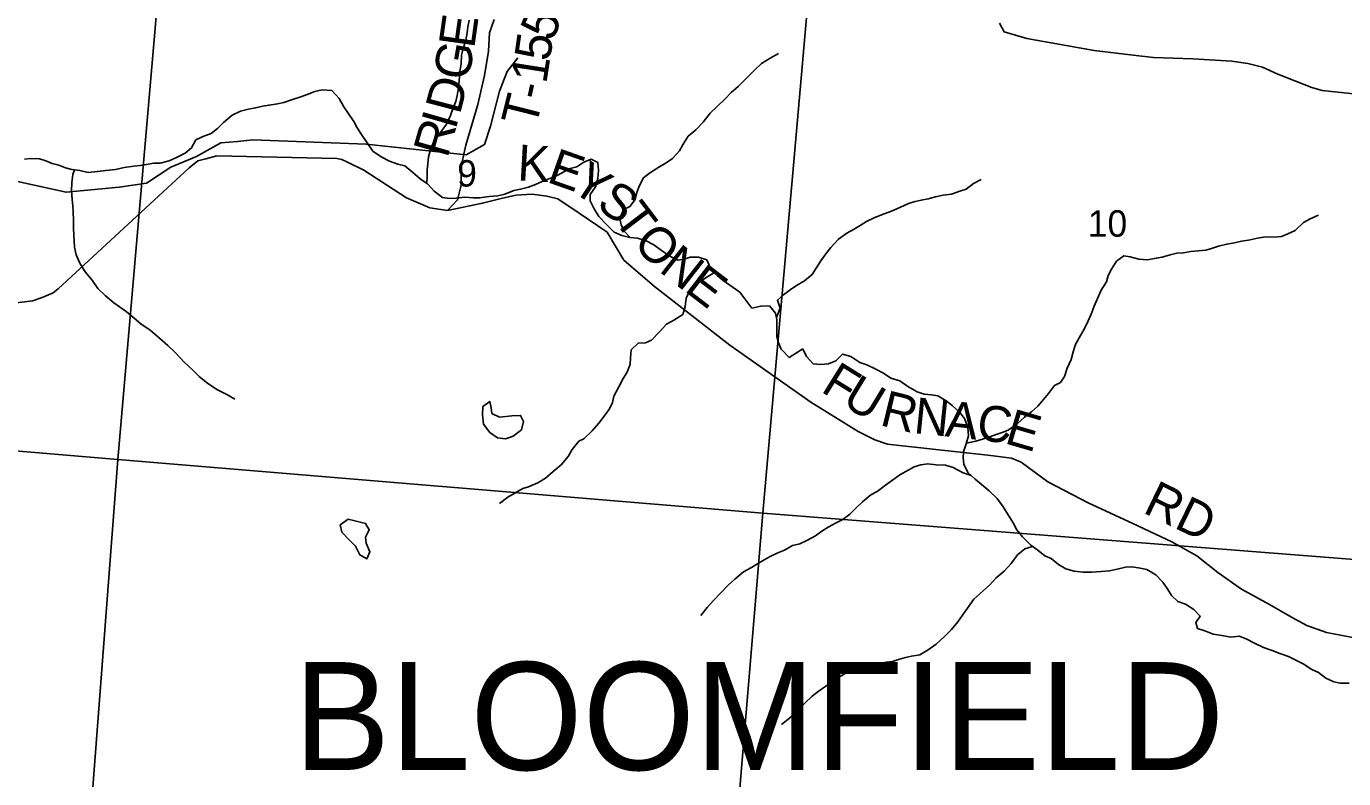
# Model space of a CAD drawing. Extents: x 0 to 42, y 0 to 22.
# Drawn here: x 6.349 to 7.389, y 18.942 to 19.536 of the extents above; entities that cross this region are included whole.
import ezdxf

# ---------------------------------------------------------------- set-up
doc = ezdxf.new("R2010")
doc.units = 0
for name, color, linetype in [('GM_X_County_Road', 7, 'Continuous'), ('GM_X_County_Road_Text', 7, 'Continuous'), ('GM_X_Minor_Lake', 7, 'Continuous'), ('GM_X_Minor_River', 7, 'Continuous'), ('GM_X_Rail_Line', 7, 'Continuous'), ('GM_X_Section', 7, 'Continuous'), ('GM_X_Section_Text', 7, 'Continuous'), ('GM_X_Township_Road', 7, 'Continuous'), ('GM_X_Township_Road_Text', 7, 'Continuous'), ('GM_X_Township_Text', 7, 'Continuous')]:
    doc.layers.add(name, color=color, linetype=linetype)

msp = doc.modelspace()

# ---------------------------------------------------------------- linework, layer by layer
at = {"layer": 'GM_X_County_Road'}
for points in [[(7.1177, 19.5388), (7.1212, 19.532), (7.1391, 19.5267), (7.1924, 19.5172), (7.2231, 19.5135), (7.2391, 19.5118), (7.2702, 19.5107), (7.301, 19.5089), (7.3136, 19.5071), (7.3253, 19.504), (7.3375, 19.4986), (7.3642, 19.488), (7.3723, 19.4858), (7.4098, 19.4816)], [(6.1908, 19.3004), (6.3543, 19.3196), (6.363, 19.3228), (6.3703, 19.3259), (6.3744, 19.329), (6.4778, 19.4246), (6.4845, 19.43), (6.4908, 19.4318), (6.4939, 19.4325), (6.4996, 19.434), (6.5943, 19.432), (6.5983, 19.4311), (6.6029, 19.429), (6.6158, 19.4227), (6.6494, 19.4009), (6.6679, 19.3929), (6.6817, 19.3909), (6.7094, 19.3967), (6.7242, 19.4005), (6.7358, 19.4029), (6.7485, 19.4037), (6.7603, 19.4023), (6.7689, 19.4001), (6.7856, 19.3889), (6.8078, 19.3737), (6.821, 19.3518), (6.8452, 19.3308), (6.9047, 19.2846), (6.9685, 19.2395), (7.0059, 19.2163), (7.0191, 19.2097), (7.0291, 19.2064), (7.0698, 19.202), (7.1083, 19.1976), (7.127, 19.1954), (7.1347, 19.1921), (7.1557, 19.1767), (7.1876, 19.1602), (7.2228, 19.1437), (7.2536, 19.1293), (7.2734, 19.1183), (7.29, 19.1051), (7.3087, 19.0919), (7.3307, 19.0798), (7.3483, 19.0699), (7.3604, 19.0633), (7.3758, 19.0578), (7.4034, 19.0523)]]:
    msp.add_lwpolyline(points, dxfattribs=at)
at = {"layer": 'GM_X_Minor_Lake'}
for points in [[(6.7227, 19.2276), (6.7168, 19.2305), (6.7161, 19.2352), (6.7152, 19.24), (6.7097, 19.2362), (6.7095, 19.2296), (6.7102, 19.2222), (6.7151, 19.2157), (6.7213, 19.2113), (6.7276, 19.2106), (6.7314, 19.212)], [(6.7314, 19.212), (6.7336, 19.2128), (6.7401, 19.2177), (6.7418, 19.2242), (6.7395, 19.2291), (6.7325, 19.2287), (6.7227, 19.2276)], [(6.6032, 19.1473), (6.597, 19.1427), (6.5983, 19.1369), (6.6039, 19.131), (6.609, 19.1258), (6.6124, 19.119), (6.6181, 19.1159), (6.6197, 19.1195)], [(6.6197, 19.1195), (6.6205, 19.1214), (6.6175, 19.1283), (6.617, 19.133), (6.62, 19.1387), (6.617, 19.1438), (6.6032, 19.1473)]]:
    msp.add_lwpolyline(points, dxfattribs=at)
at = {"layer": 'GM_X_Minor_River'}
for points in [[(6.6651, 19.4125), (6.6656, 19.4163), (6.6658, 19.4229), (6.6662, 19.4277), (6.6668, 19.4334), (6.6686, 19.4398), (6.6714, 19.4466), (6.6767, 19.4534), (6.6809, 19.4591), (6.684, 19.4659), (6.6861, 19.472), (6.6882, 19.4769), (6.6893, 19.4818), (6.6905, 19.4875), (6.6909, 19.4932), (6.6915, 19.5004), (6.6924, 19.5069), (6.6928, 19.5135), (6.694, 19.5188), (6.6961, 19.5254), (6.6973, 19.5311), (6.6978, 19.5359), (6.6988, 19.5413)], [(6.826, 19.3697), (6.821, 19.3749), (6.8188, 19.3796), (6.8177, 19.3847), (6.8207, 19.3917), (6.8258, 19.394), (6.83, 19.3997), (6.8312, 19.405), (6.8333, 19.4106), (6.8365, 19.4167), (6.8413, 19.4203), (6.8485, 19.425), (6.8545, 19.4286), (6.8593, 19.432), (6.8648, 19.438), (6.8678, 19.4433), (6.8718, 19.4496), (6.8779, 19.4545), (6.8836, 19.4607), (6.8891, 19.4677), (6.8948, 19.4732), (6.9007, 19.4787), (6.9056, 19.484), (6.9113, 19.4889), (6.9242, 19.5017), (6.9297, 19.5069), (6.9364, 19.5112), (6.9432, 19.5148)], [(6.7893, 19.429), (6.7839, 19.4254), (6.7786, 19.4241), (6.7735, 19.4214), (6.7682, 19.4186), (6.7618, 19.416), (6.7565, 19.4137), (6.7513, 19.4115), (6.7458, 19.4094), (6.7394, 19.4077), (6.7341, 19.4066), (6.7271, 19.4038), (6.7214, 19.4025), (6.7146, 19.4019), (6.7072, 19.4008), (6.7021, 19.401), (6.6955, 19.4014), (6.6885, 19.4007), (6.6836, 19.4005), (6.6779, 19.4011), (6.6711, 19.4061), (6.666, 19.412), (6.6601, 19.4158), (6.6541, 19.4213), (6.6481, 19.4262), (6.6426, 19.4276), (6.636, 19.4299), (6.6294, 19.4333), (6.6228, 19.4377), (6.6184, 19.4443), (6.6139, 19.4508), (6.6105, 19.4563), (6.6079, 19.4613), (6.6034, 19.4677), (6.5998, 19.4729), (6.5962, 19.4793), (6.5904, 19.4856), (6.5828, 19.4862), (6.5769, 19.4849), (6.5709, 19.4826), (6.5659, 19.4807), (6.5586, 19.4783), (6.5525, 19.4762), (6.5474, 19.4751), (6.5408, 19.4742), (6.5358, 19.4733), (6.53, 19.4721), (6.5247, 19.471), (6.5182, 19.4693), (6.5116, 19.4663), (6.5049, 19.4603), (6.5, 19.4556), (6.4951, 19.4516), (6.4892, 19.4495), (6.4831, 19.4467), (6.4795, 19.4403), (6.4746, 19.4361), (6.4678, 19.4327), (6.4619, 19.4301), (6.4549, 19.4284), (6.4496, 19.4282), (6.4441, 19.4273), (6.439, 19.4264), (6.434, 19.426), (6.4265, 19.4249), (6.4197, 19.4234), (6.4119, 19.4225), (6.4053, 19.4216), (6.3981, 19.421), (6.3915, 19.4224), (6.3852, 19.4233), (6.3801, 19.4247), (6.3748, 19.4268), (6.3695, 19.4281), (6.3646, 19.43), (6.3595, 19.4318), (6.3527, 19.432), (6.3478, 19.4314)], [(7.0259, 19.2624), (7.0194, 19.266), (7.0128, 19.2691), (7.0074, 19.271), (7.0002, 19.2756), (6.9936, 19.2775), (6.9884, 19.2722), (6.9826, 19.2698), (6.9763, 19.2694), (6.9706, 19.2698), (6.9653, 19.2755), (6.9623, 19.2816), (6.9572, 19.2785), (6.9515, 19.2748), (6.9451, 19.2814), (6.9432, 19.2864), (6.9419, 19.2913), (6.9418, 19.2985), (6.9418, 19.3049), (6.9408, 19.3099), (6.9359, 19.3156), (6.9291, 19.3154), (6.9221, 19.3137), (6.9172, 19.3202), (6.9125, 19.3263), (6.9074, 19.3301), (6.8995, 19.3356), (6.8946, 19.3396), (6.8893, 19.3455), (6.8865, 19.3519), (6.88, 19.354), (6.8734, 19.354), (6.8685, 19.3525), (6.8636, 19.3516), (6.8579, 19.3547), (6.8515, 19.3588), (6.8447, 19.3638), (6.8381, 19.3672), (6.8314, 19.3691), (6.8258, 19.3697), (6.8195, 19.3713), (6.8133, 19.3737), (6.8069, 19.3802), (6.8012, 19.3863), (6.7976, 19.3922), (6.7944, 19.3986), (6.7943, 19.4036), (6.7986, 19.4096), (6.8004, 19.4161), (6.8009, 19.4225), (6.8004, 19.4289), (6.7952, 19.4315), (6.7893, 19.429)], [(6.3871, 19.423), (6.3858, 19.4193), (6.385, 19.4129), (6.3848, 19.4065), (6.3853, 19.3996), (6.3859, 19.3947), (6.3861, 19.3898), (6.3864, 19.3831), (6.3864, 19.3767), (6.3867, 19.3717), (6.3869, 19.3668), (6.3873, 19.3619), (6.3886, 19.3558), (6.3914, 19.3494), (6.3957, 19.3425), (6.4012, 19.336), (6.4055, 19.3294), (6.4116, 19.3235), (6.4182, 19.318), (6.428, 19.3111), (6.4342, 19.306), (6.4395, 19.3014), (6.447, 19.2963), (6.4542, 19.2902), (6.461, 19.2843), (6.4672, 19.2782), (6.4738, 19.2711), (6.4804, 19.2652), (6.4857, 19.2599), (6.4925, 19.2544), (6.5002, 19.2494), (6.5074, 19.2456), (6.5138, 19.242)], [(6.9415, 19.3063), (6.9443, 19.3138), (6.9422, 19.3201), (6.9471, 19.3244), (6.9523, 19.3282), (6.9572, 19.3318), (6.9636, 19.3354), (6.9697, 19.3405), (6.9728, 19.3454), (6.9764, 19.3511), (6.9806, 19.3568), (6.9844, 19.3617), (6.9904, 19.3683), (6.9971, 19.373), (7.0022, 19.376), (7.0077, 19.3792), (7.0126, 19.3823), (7.0187, 19.3851), (7.0257, 19.3881), (7.0323, 19.3905), (7.039, 19.3932), (7.0458, 19.3964), (7.0511, 19.3981), (7.0558, 19.399), (7.0613, 19.4001), (7.067, 19.4016), (7.0731, 19.4029), (7.0797, 19.4039), (7.0863, 19.4061), (7.0913, 19.4078), (7.0971, 19.4122), (7.1032, 19.4155)], [(7.0915, 19.2072), (7.099, 19.2088), (7.1043, 19.2103), (7.1101, 19.2121), (7.1151, 19.214), (7.1198, 19.2155), (7.1245, 19.2174), (7.1316, 19.2225), (7.1373, 19.2276), (7.1431, 19.2323), (7.1479, 19.2365), (7.1524, 19.2416), (7.1564, 19.2465), (7.161, 19.2526), (7.1657, 19.255), (7.1688, 19.2599), (7.1711, 19.2664), (7.1741, 19.2732), (7.1755, 19.2783), (7.1774, 19.2847), (7.1804, 19.2904), (7.1844, 19.2972), (7.1875, 19.3037), (7.1899, 19.3091), (7.1924, 19.3154), (7.1951, 19.3213), (7.1979, 19.3279), (7.2021, 19.3347), (7.2035, 19.3396), (7.206, 19.3445), (7.2101, 19.3508), (7.2158, 19.3551), (7.2209, 19.3542), (7.2277, 19.3526), (7.2344, 19.352), (7.2414, 19.3532), (7.2461, 19.3541), (7.2524, 19.356), (7.2577, 19.3571), (7.2628, 19.3575), (7.2688, 19.3586), (7.2747, 19.3591), (7.2804, 19.3597), (7.2851, 19.3608), (7.2906, 19.3627), (7.2971, 19.3644), (7.3031, 19.3655), (7.3088, 19.3668), (7.3141, 19.3674), (7.3213, 19.369), (7.3277, 19.37), (7.3344, 19.3698), (7.3404, 19.3705), (7.3454, 19.3726), (7.3512, 19.375), (7.3577, 19.3814), (7.363, 19.3843), (7.3694, 19.3871)], [(6.8925, 19.3419), (6.886, 19.3381), (6.8794, 19.3336), (6.8731, 19.3277), (6.8701, 19.3216), (6.8695, 19.3152), (6.8676, 19.3088), (6.8604, 19.3044), (6.8547, 19.3012), (6.8492, 19.295), (6.8427, 19.2884), (6.838, 19.2863), (6.8323, 19.2861), (6.8268, 19.281), (6.8262, 19.2746), (6.826, 19.2696), (6.8235, 19.2632), (6.8205, 19.2583), (6.8169, 19.2517), (6.8131, 19.2443), (6.8121, 19.2394), (6.8096, 19.2344), (6.8062, 19.2295), (6.8013, 19.2231), (6.7959, 19.217), (6.7893, 19.2107)], [(7.3936, 19.0176), (7.3866, 19.0178), (7.3817, 19.0188), (7.3753, 19.0216), (7.3694, 19.0262), (7.3643, 19.0285), (7.3573, 19.0329), (7.352, 19.0355), (7.3458, 19.0388), (7.339, 19.0412), (7.3328, 19.0434), (7.326, 19.0458), (7.319, 19.0493), (7.3125, 19.0527), (7.3069, 19.0548), (7.3002, 19.0541), (7.2932, 19.0554), (7.2862, 19.0564), (7.2798, 19.0589), (7.274, 19.0608), (7.2726, 19.0657), (7.2761, 19.0706), (7.271, 19.0758), (7.2644, 19.0801), (7.2583, 19.0822), (7.2534, 19.087), (7.2506, 19.0917), (7.2466, 19.0974), (7.241, 19.1031), (7.234, 19.1075), (7.2274, 19.1087), (7.2222, 19.1096), (7.2171, 19.1093), (7.2105, 19.1078), (7.2044, 19.1065), (7.198, 19.1059), (7.1902, 19.1054), (7.1836, 19.1052), (7.1766, 19.1062), (7.17, 19.1079), (7.1643, 19.1113), (7.1583, 19.1161), (7.1534, 19.1182), (7.1479, 19.1226), (7.1424, 19.1266), (7.1358, 19.1332), (7.1313, 19.1387), (7.1283, 19.1442), (7.1245, 19.1507), (7.1204, 19.1569), (7.1157, 19.1636), (7.1094, 19.1695), (7.1032, 19.1748), (7.0983, 19.1788), (7.0926, 19.1841), (7.0894, 19.1906), (7.0889, 19.1955), (7.0893, 19.2004), (7.0914, 19.2067), (7.0931, 19.2129), (7.0927, 19.2196), (7.0899, 19.2266), (7.0862, 19.2315), (7.0803, 19.2369), (7.0754, 19.2405), (7.0688, 19.2445), (7.0639, 19.2453), (7.058, 19.2458), (7.0527, 19.2477), (7.0453, 19.2519), (7.0389, 19.2563), (7.0319, 19.2586), (7.0259, 19.2624)], [(6.7893, 19.2107), (6.7855, 19.2087), (6.7803, 19.2022), (6.7771, 19.1966), (6.7716, 19.1901), (6.7651, 19.1848), (6.7591, 19.1795), (6.753, 19.176), (6.7458, 19.1728), (6.7411, 19.1713), (6.7361, 19.1686), (6.7295, 19.1645), (6.7227, 19.1596)], [(7.0953, 19.1816), (7.0888, 19.1838), (7.0809, 19.188), (7.0749, 19.1899), (7.0677, 19.1901), (7.0609, 19.1909), (7.0554, 19.1901), (7.0502, 19.1884), (7.0436, 19.1848), (7.0389, 19.1822), (7.0324, 19.1775), (7.0275, 19.1741), (7.021, 19.169), (7.0161, 19.1663), (7.0095, 19.1609), (7.0045, 19.1561), (6.9994, 19.151), (6.9939, 19.1469), (6.988, 19.1439), (6.9823, 19.1409), (6.9774, 19.1378), (6.9723, 19.1341), (6.9656, 19.1303), (6.96, 19.1278), (6.9541, 19.1263), (6.9478, 19.1226), (6.9425, 19.1207), (6.9359, 19.1175), (6.9285, 19.1133), (6.9217, 19.109), (6.9154, 19.1056), (6.9086, 19.0998), (6.9034, 19.095), (6.8972, 19.0888), (6.8919, 19.0829), (6.8869, 19.0773), (6.8818, 19.071)], [(7.1436, 19.1257), (7.1377, 19.1237), (7.1318, 19.119), (7.1269, 19.1122), (7.1213, 19.1061), (7.1149, 19.1009), (7.1096, 19.095), (7.0974, 19.084), (7.0923, 19.077), (7.0883, 19.0715), (7.0847, 19.0661), (7.0797, 19.06), (7.0741, 19.0545), (7.0676, 19.0485), (7.0613, 19.0441), (7.0547, 19.04), (7.0481, 19.0389), (7.0433, 19.0379), (7.0378, 19.0364), (7.0331, 19.0347), (7.028, 19.0342), (7.0231, 19.0335), (7.0161, 19.0333), (7.0102, 19.0314), (7.0049, 19.0295), (7.0001, 19.0275), (6.9952, 19.025), (6.988, 19.0207), (6.9804, 19.0152), (6.9745, 19.011), (6.9696, 19.0074), (6.9639, 19.0018), (6.9582, 18.9955), (6.9519, 18.9901), (6.9455, 18.985)]]:
    msp.add_lwpolyline(points, dxfattribs=at)
at = {"layer": 'GM_X_Rail_Line'}
msp.add_lwpolyline([(6.1031, 19.4971), (6.1186, 19.4683), (6.1371, 19.4616), (6.1548, 19.4548), (6.3805, 19.4053), (6.4226, 19.4093), (6.4441, 19.4126), (6.4632, 19.4252), (6.4836, 19.4336), (6.5027, 19.4444), (6.5159, 19.4455), (6.5279, 19.4467), (6.6176, 19.4432), (6.6966, 19.4348), (6.711, 19.4431), (6.7157, 19.4575), (6.7229, 19.4851), (6.7289, 19.5006), (6.7373, 19.5114)], dxfattribs=at)
at = {"layer": 'GM_X_Section'}
for points in [[(5.9652, 19.7427), (6.4653, 19.7024), (6.4215, 19.1942), (5.9249, 19.2362)], [(6.4653, 19.7024), (6.9755, 19.66), (6.9308, 19.1519), (6.4215, 19.1942)], [(7.4728, 19.6259), (7.4347, 19.1125), (6.9308, 19.1519), (6.9755, 19.66)], [(5.9249, 19.2362), (6.4215, 19.1942), (6.3828, 18.6867), (5.8869, 18.7234)], [(6.4215, 19.1942), (6.9308, 19.1519), (6.889, 18.6514), (6.3828, 18.6867)], [(6.9308, 19.1519), (7.4347, 19.1125), (7.3969, 18.6082), (6.889, 18.6514)]]:
    msp.add_lwpolyline(points, close=True, dxfattribs=at)
at = {"layer": 'GM_X_Township_Road'}
msp.add_lwpolyline([(6.6817, 19.3909), (6.6897, 19.3993), (6.6925, 19.4108), (6.6929, 19.427), (6.6961, 19.4426), (6.7056, 19.4747), (6.7109, 19.4976), (6.714, 19.5168), (6.715, 19.5311), (6.7187, 19.5417)], dxfattribs=at)

# ---------------------------------------------------------------- texts
at = {"layer": 'GM_X_County_Road_Text'}
for s, height, rotation, p in [('K', 0.0284, 356.8, (6.7365, 19.4147)), ('E', 0.0284, 340.5757, (6.7593, 19.4137)), ('Y', 0.0284, 326.3695, (6.7777, 19.4075)), ('S', 0.0284, 323.5796, (6.7982, 19.3938)), ('T', 0.0284, 307.2333, (6.8121, 19.3839)), ('O', 0.0284, 313.8841, (6.8273, 19.3643)), ('N', 0.0284, 321.9601, (6.8479, 19.3433)), ('E', 0.0284, 322.5397, (6.8679, 19.3278)), ('F', 0.0284, 328.179, (6.9757, 19.2484)), ('U', 0.0284, 328.7265, (6.9922, 19.2381)), ('R', 0.0284, 346.1737, (7.0223, 19.2216)), ('N', 0.0284, 354.0802, (7.0492, 19.2152)), ('A', 0.0284, 353.6852, (7.074, 19.2127)), ('C', 0.0284, 353.2676, (7.0988, 19.2099)), ('E', 0.0284, 343.6567, (7.1207, 19.2074)), ('RD', 0.02841, 334.0903, (7.2299, 19.1528))]:
    msp.add_text(s, height=height, rotation=rotation, dxfattribs=at).set_placement(p)
at = {"layer": 'GM_X_Section_Text'}
for s, height, p in [('9', 0.0209, (6.6894, 19.4098)), ('10', 0.02093, (7.1873, 19.3702))]:
    msp.add_text(s, height=height, rotation=0, dxfattribs=at).set_placement(p)
at = {"layer": 'GM_X_Township_Road_Text'}
for s, rotation, p in [('E', 82.0023, (6.7028, 19.5183)), ('5', 66.921, (6.7644, 19.5235)), ('5', 81.8574, (6.7625, 19.5081)), ('G', 80.1601, (6.6983, 19.4927)), ('1', 81.1294, (6.7597, 19.4904)), ('D', 75.285, (6.6914, 19.4659)), ('T', 75.8286, (6.7514, 19.4556)), ('-', 77.6012, (6.7569, 19.4771)), ('R', 73.9243, (6.6816, 19.4316)), ('I', 74.0258, (6.688, 19.454))]:
    msp.add_text(s, height=0.0284, rotation=rotation, dxfattribs=at).set_placement(p)
at = {"layer": 'GM_X_Township_Text'}
msp.add_text('BLOOMFIELD', height=0.08523, rotation=0, dxfattribs=at).set_placement((6.5604, 18.9491))

doc.saveas('drawing.dxf')
